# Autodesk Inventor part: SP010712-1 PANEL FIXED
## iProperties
Created: 2013-01
Part Number: SP010712-1 PANEL FIXED
Material: Polycarbonate, Clear
Document SubType Name: Modeling
Designer: Administrator
Mass: 3789.16 g
Surface Area: 11470.7 cm^2
Volume: 3157.63 cm^3
Density: 1.2 g/cm^3
Author: Administrator
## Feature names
1. Extrusion1
2. Hole1
